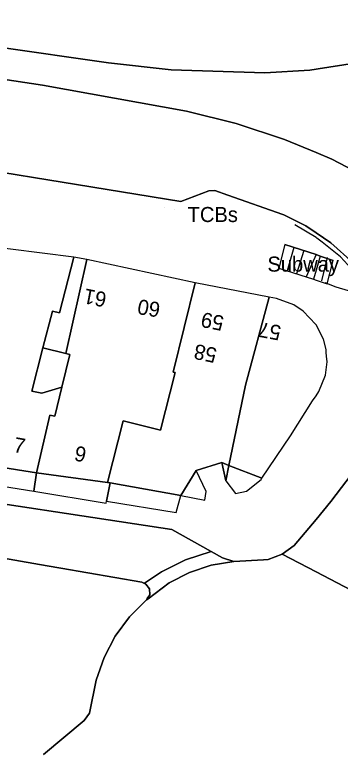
# Model space of a CAD drawing. Extents: x 529240 to 530363, y 179600 to 180767.
# Drawn here: x 529969.9 to 530002.4, y 180321.7 to 180395.2 of the extents above; entities that cross this region are included whole.
import ezdxf

# ---------------------------------------------------------------- set-up
doc = ezdxf.new("R2010")
doc.units = 0
for name, color, linetype in [('Building', 7, 'Continuous'), ('General surface', 7, 'Continuous'), ('Road Or Track', 7, 'Continuous'), ('Roadside', 7, 'Continuous'), ('Structure', 7, 'Continuous'), ('Unclassified', 7, 'Continuous')]:
    doc.layers.add(name, color=color, linetype=linetype)

msp = doc.modelspace()

# ---------------------------------------------------------------- linework, layer by layer
at = {"layer": 'Building'}
for points in [[(529968.1, 180350.2), (529972.1, 180349.55), (529973.45, 180355.3), (529973.95, 180355.2), (529974.65, 180358.1), (529972.65, 180357.5), (529971.65, 180357.7), (529972.75, 180362), (529973.7, 180365.65), (529974.4, 180365.5), (529975.85, 180371.05), (529960, 180373.05), (529957.55, 180360.3), (529963.4, 180359.2), (529962.95, 180357), (529962.5, 180357.05), (529961.45, 180351.2), (529964.45, 180350.75)], [(529979.2, 180348.6), (529980.75, 180354.75), (529984.5, 180353.8), (529985.95, 180359.55), (529985.75, 180359.6), (529987.95, 180368.5), (529977.15, 180370.8), (529975.05, 180361.45), (529975.45, 180361.35), (529974.65, 180358.1), (529973.95, 180355.2), (529973.45, 180355.3), (529972.1, 180349.55)], [(529977.15, 180370.8), (529975.85, 180371.05), (529974.4, 180365.5), (529973.7, 180365.65), (529972.75, 180362), (529975.05, 180361.45)], [(529979.45, 180348.55), (529986.5, 180347.3), (529988.05, 180349.8), (529990.6, 180350.6), (529991.3, 180350.3), (529992.95, 180358.3), (529995.33, 180367.05), (529987.95, 180368.5), (529985.75, 180359.6), (529985.95, 180359.55), (529984.5, 180353.8), (529980.75, 180354.75), (529979.2, 180348.6)], [(529999.65, 180356.74), (530000, 180357.24), (530000.28, 180357.66), (530000.93, 180359.29), (530001.1, 180360.6), (530001.05, 180361.18), (530001.02, 180361.56), (530001, 180361.86), (530000.73, 180362.89), (530000, 180364.31), (529999.99, 180364.33), (529998.73, 180365.67), (529997.78, 180366.3), (529996.06, 180366.91), (529995.33, 180367.05), (529992.95, 180358.3), (529991.3, 180350.3), (529994.59, 180349.02), (529997.44, 180353.25)]]:
    msp.add_lwpolyline(points, close=True, dxfattribs=at)
for points in [[(529975.85, 180371.05), (529960, 180373.05)], [(529972.75, 180362), (529973.7, 180365.65), (529974.4, 180365.5), (529975.85, 180371.05)], [(529975.05, 180361.45), (529977.15, 180370.8)], [(529977.15, 180370.8), (529975.85, 180371.05)], [(529987.95, 180368.5), (529977.15, 180370.8)], [(529979.2, 180348.6), (529980.75, 180354.75), (529984.5, 180353.8), (529985.95, 180359.55), (529985.75, 180359.6), (529987.95, 180368.5)], [(529995.33, 180367.05), (529987.95, 180368.5)], [(529995.33, 180367.05), (529992.95, 180358.3), (529991.3, 180350.3)], [(529999.65, 180356.74), (530000, 180357.24), (530000.28, 180357.66), (530000.93, 180359.29), (530001.1, 180360.6), (530001.05, 180361.18), (530001.02, 180361.56), (530001, 180361.86), (530000.73, 180362.89), (530000, 180364.31), (529999.99, 180364.33), (529998.73, 180365.67), (529997.78, 180366.3), (529996.06, 180366.91), (529995.33, 180367.05)], [(529974.65, 180358.1), (529972.65, 180357.5), (529971.65, 180357.7), (529972.75, 180362)], [(529975.05, 180361.45), (529972.75, 180362)], [(529974.65, 180358.1), (529975.45, 180361.35), (529975.05, 180361.45)], [(529972.1, 180349.55), (529973.45, 180355.3), (529973.95, 180355.2), (529974.65, 180358.1)], [(529994.59, 180349.02), (529997.44, 180353.25), (529999.65, 180356.74)], [(529968.1, 180350.2), (529972.1, 180349.55)], [(529990.6, 180350.6), (529988.05, 180349.8)], [(529991.3, 180350.3), (529990.6, 180350.6)], [(529994.59, 180349.02), (529991.3, 180350.3)], [(529972.1, 180349.55), (529979.2, 180348.6)], [(529988.05, 180349.8), (529986.5, 180347.3)], [(529979.2, 180348.6), (529979.45, 180348.55)], [(529979.45, 180348.55), (529986.5, 180347.3)]]:
    msp.add_lwpolyline(points, dxfattribs=at)
at = {"layer": 'General surface'}
for points in [[(529996.9, 180372.3), (529996.3, 180369.95), (529999.75, 180368.85), (530000, 180368.75), (530001.1, 180368.4), (530001.7, 180370.7), (530000.4, 180371.15), (530000, 180371.3)], [(529974.65, 180358.1), (529975.45, 180361.35), (529975.05, 180361.45), (529972.75, 180362), (529971.65, 180357.7), (529972.65, 180357.5)], [(529971.85, 180347.75), (529972.1, 180349.55), (529968.1, 180350.2), (529967.85, 180348.35)], [(529991.3, 180350.3), (529990.6, 180350.6), (529991, 180348.75)], [(529991.3, 180350.3), (529991, 180348.75), (529991.95, 180347.5), (529993.05, 180347.75), (529994.51, 180348.9), (529994.59, 180349.02)], [(529979.2, 180348.6), (529972.1, 180349.55), (529971.85, 180347.75), (529979.05, 180346.55), (529979.1, 180346.75), (529979.45, 180348.55)], [(529986.5, 180347.3), (529988.9, 180346.85), (529989.05, 180347.7), (529988.05, 180349.8)], [(529979.45, 180348.55), (529979.1, 180346.75), (529986.05, 180345.6), (529986.5, 180347.3)]]:
    msp.add_lwpolyline(points, close=True, dxfattribs=at)
for points in [[(529996.9, 180372.3), (529996.3, 180369.95)], [(529997.8, 180372.01), (529997.12, 180369.69)], [(529998.78, 180371.69), (529998.05, 180369.39)], [(530000, 180371.3), (529999, 180369.09)], [(530000.4, 180371.15), (530000, 180369.75), (529999.75, 180368.85)], [(530001.1, 180371), (530000.55, 180368.7)]]:
    msp.add_lwpolyline(points, dxfattribs=at)
at = {"layer": 'Road Or Track'}
for points in [[(529954.48, 180398.5), (529953.23, 180394.13), (529953.97, 180394.02), (529956.99, 180393.59), (529979.3, 180390.4), (529985.56, 180389.7), (529994.89, 180389.4), (529999.38, 180389.68), (530000, 180389.77), (530000.2, 180389.8), (530003.82, 180390.38), (530011.94, 180392.6), (530010.83, 180400.08)], [(530011.94, 180392.6), (530003.82, 180390.38), (530000.2, 180389.8), (530000, 180389.77), (529999.38, 180389.68), (529994.89, 180389.4), (529985.56, 180389.7), (529979.3, 180390.4), (529956.99, 180393.59), (529953.97, 180394.02), (529953.23, 180394.13)], [(529952.41, 180391.23), (529952.45, 180391.21), (529953.54, 180391.05), (529972.72, 180388.17), (529987.07, 180385.57), (529992.02, 180384.36), (529996.86, 180382.76), (530000, 180381.45), (530001.57, 180380.79), (530006.1, 180378.46)], [(529949.92, 180382.52), (529952.4, 180382.12), (529955.46, 180381.62), (529986.51, 180376.59), (529989.29, 180377.65), (529989.92, 180377.68), (529991.21, 180377.23), (529996.68, 180375.3), (529996.77, 180375.26), (529998.99, 180374.16), (530000, 180373.48), (530001.47, 180372.48), (530003.69, 180370.47), (530005.28, 180368.4)], [(530007.46, 180362.76), (530007.67, 180360.38), (530007.5, 180357.98), (530007.09, 180356.28), (530006.94, 180355.65), (530006.23, 180353.98), (530005.88, 180353.16), (530005.52, 180352.55), (530004.04, 180350.06), (530001.49, 180346.7), (530000, 180344.91), (529997.83, 180342.33), (529996.61, 180341.47)], [(529989.55, 180341.72), (529985.6, 180343.91), (529959.75, 180347.85), (529942.9, 180350.6), (529942.65, 180350.7), (529941.9, 180351.15)], [(530004.04, 180350.06), (530001.49, 180346.7), (530000, 180344.91), (529997.83, 180342.33), (529996.61, 180341.47), (530000, 180339.7), (530003.49, 180337.87)], [(529973.18, 180340.31), (529941.05, 180345.9), (529940.34, 180346.04)], [(530003.49, 180337.87), (530000, 180339.7), (529996.61, 180341.47), (529995.21, 180340.94), (529994.77, 180340.91), (529991.8, 180340.74), (529989.55, 180340.36), (529987.39, 180339.63), (529985.36, 180338.6), (529983.24, 180337.02), (529983.09, 180336.91), (529981.4, 180335.22), (529979.97, 180333.29), (529978.85, 180331.17), (529978.06, 180328.91), (529977.41, 180325.61), (529976.87, 180324.9), (529972.82, 180321.51)], [(529989.55, 180341.72), (529986.98, 180340.9), (529984.57, 180339.7), (529982.9, 180338.56), (529982.88, 180338.55)], [(529991.8, 180340.74), (529990.67, 180341.1), (529989.55, 180341.72)], [(529996.61, 180341.47), (529995.21, 180340.94), (529994.77, 180340.91), (529991.8, 180340.74)], [(529991.8, 180340.74), (529989.55, 180340.36), (529987.39, 180339.63), (529985.36, 180338.6), (529983.24, 180337.02), (529983.09, 180336.91)], [(529982.88, 180338.55), (529982.61, 180338.66), (529974.53, 180340.07), (529973.18, 180340.31)], [(529983.09, 180336.91), (529983.17, 180337.03), (529983.41, 180337.41), (529983.39, 180338.01), (529983.03, 180338.48), (529982.88, 180338.55)], [(529972.82, 180321.51), (529976.87, 180324.9), (529977.41, 180325.61), (529978.06, 180328.91), (529978.85, 180331.17), (529979.97, 180333.29), (529981.4, 180335.22), (529983.09, 180336.91)]]:
    msp.add_lwpolyline(points, dxfattribs=at)
for points in [[(530005.28, 180368.4), (530006.1, 180378.46), (530001.57, 180380.79), (530000, 180381.45), (529996.86, 180382.76), (529992.02, 180384.36), (529987.07, 180385.57), (529972.72, 180388.17), (529953.54, 180391.05), (529952.45, 180391.21), (529952.41, 180391.23), (529949.92, 180382.52), (529952.4, 180382.12), (529955.46, 180381.62), (529986.51, 180376.59), (529989.29, 180377.65), (529989.92, 180377.68), (529991.21, 180377.23), (529996.68, 180375.3), (529996.77, 180375.26), (529998.99, 180374.16), (530000, 180373.48), (530001.47, 180372.48), (530003.69, 180370.47)], [(529940.34, 180346.04), (529941.05, 180345.9), (529973.18, 180340.31), (529974.53, 180340.07), (529982.61, 180338.66), (529982.88, 180338.55), (529982.9, 180338.56), (529984.57, 180339.7), (529986.98, 180340.9), (529989.55, 180341.72), (529985.6, 180343.91), (529959.75, 180347.85), (529942.9, 180350.6), (529942.65, 180350.7), (529941.9, 180351.15)], [(529983.09, 180336.91), (529983.24, 180337.02), (529985.36, 180338.6), (529987.39, 180339.63), (529989.55, 180340.36), (529991.8, 180340.74), (529990.67, 180341.1), (529989.55, 180341.72), (529986.98, 180340.9), (529984.57, 180339.7), (529982.9, 180338.56), (529982.88, 180338.55), (529983.03, 180338.48), (529983.39, 180338.01), (529983.41, 180337.41), (529983.17, 180337.03)]]:
    msp.add_lwpolyline(points, close=True, dxfattribs=at)
at = {"layer": 'Roadside'}
for points in [[(530003.82, 180390.38), (530000.2, 180389.8), (530000, 180389.77), (529999.38, 180389.68), (529994.89, 180389.4), (529985.56, 180389.7), (529979.3, 180390.4), (529956.99, 180393.59)], [(529953.54, 180391.05), (529972.72, 180388.17), (529987.07, 180385.57), (529992.02, 180384.36), (529996.86, 180382.76), (530000, 180381.45), (530001.57, 180380.79), (530006.1, 180378.46)], [(530003.69, 180370.47), (530001.47, 180372.48), (530000, 180373.48), (529998.99, 180374.16), (529996.77, 180375.26), (529996.68, 180375.3), (529991.21, 180377.23), (529989.92, 180377.68), (529989.29, 180377.65), (529986.51, 180376.59), (529955.46, 180381.62)], [(529967.85, 180348.35), (529971.85, 180347.75), (529979.05, 180346.55), (529979.1, 180346.75), (529986.05, 180345.6), (529986.5, 180347.3), (529988.9, 180346.85), (529989.05, 180347.7), (529988.05, 180349.8), (529990.6, 180350.6), (529991, 180348.75), (529991.95, 180347.5), (529993.05, 180347.75), (529994.51, 180348.9), (529994.59, 180349.02), (529997.44, 180353.25), (529999.65, 180356.74), (530000, 180357.24), (530000.28, 180357.66), (530000.93, 180359.29), (530001.1, 180360.6), (530001.05, 180361.18), (530001.02, 180361.56), (530001, 180361.86), (530000.73, 180362.89), (530000, 180364.31), (529999.99, 180364.33), (529998.73, 180365.67), (529997.78, 180366.3), (529996.06, 180366.91), (529995.33, 180367.05), (529987.95, 180368.5), (529977.15, 180370.8), (529975.85, 180371.05), (529960, 180373.05)], [(529959.75, 180347.85), (529985.6, 180343.91), (529989.55, 180341.72), (529990.67, 180341.1), (529991.8, 180340.74), (529994.77, 180340.91), (529995.21, 180340.94), (529996.61, 180341.47), (529997.83, 180342.33), (530000, 180344.91), (530001.49, 180346.7), (530004.04, 180350.06)], [(529972.82, 180321.51), (529976.87, 180324.9), (529977.41, 180325.61), (529978.06, 180328.91), (529978.85, 180331.17), (529979.97, 180333.29), (529981.4, 180335.22), (529983.09, 180336.91), (529983.17, 180337.03), (529983.41, 180337.41), (529983.39, 180338.01), (529983.03, 180338.48), (529982.88, 180338.55), (529982.61, 180338.66), (529974.53, 180340.07), (529973.18, 180340.31), (529941.05, 180345.9)]]:
    msp.add_lwpolyline(points, dxfattribs=at)
msp.add_lwpolyline([(530000, 180371.3), (529996.9, 180372.3), (529996.3, 180369.95), (529999.75, 180368.85), (530000, 180368.75), (530001.1, 180368.4), (530001.7, 180370.7), (530000.4, 180371.15)], close=True, dxfattribs=at)
at = {"layer": 'Structure'}
for p, q in [((529984.89, 180375.94), (529984.89, 180375.94)), ((529985.87, 180375.78), (529985.87, 180375.78))]:
    msp.add_line(p, q, dxfattribs=at)
at = {"layer": 'Unclassified'}
for points in [[(530007, 180357.74), (530007.22, 180360.13), (530007.05, 180362.52), (530006.48, 180364.85), (530005.55, 180367.06), (530004.29, 180369.06), (530004.27, 180369.09), (530002.44, 180371.07), (530000.6, 180372.52), (530000.09, 180372.93), (530000, 180372.99), (529997.87, 180374.25)], [(529996.9, 180372.3), (530000, 180371.3)], [(530000, 180371.3), (530000.4, 180371.15), (530001.7, 180370.7)], [(529999.75, 180368.85), (530000, 180368.75), (530001.1, 180368.4), (530001.7, 180370.7)], [(529996.3, 180369.95), (529999.75, 180368.85)], [(530003.25, 180367.7), (530002, 180368.05), (530000.9, 180368.5)], [(529991, 180348.75), (529990.6, 180350.6)], [(529991, 180348.75), (529991.3, 180350.3)], [(529971.85, 180347.75), (529972.1, 180349.55)], [(529988.9, 180346.85), (529989.05, 180347.7), (529988.05, 180349.8)], [(529979.1, 180346.75), (529979.45, 180348.55)], [(529991, 180348.75), (529991.95, 180347.5), (529993.05, 180347.75), (529994.51, 180348.9), (529994.59, 180349.02)], [(529967.85, 180348.35), (529971.85, 180347.75)], [(529971.85, 180347.75), (529979.05, 180346.55), (529979.1, 180346.75)], [(529979.1, 180346.75), (529986.05, 180345.6), (529986.5, 180347.3)], [(529986.5, 180347.3), (529988.9, 180346.85)], [(530003.49, 180337.87), (530000, 180339.7), (529996.61, 180341.47)]]:
    msp.add_lwpolyline(points, dxfattribs=at)

# ---------------------------------------------------------------- texts
at = {"layer": 'Structure'}
for s, p in [('TCBs', (529987.19, 180374.54)), ('Subway', (529995.15, 180369.6))]:
    msp.add_text(s, height=1.5, dxfattribs=at).set_placement(p)
at = {"layer": 'Unclassified'}
for s, rotation, p in [('61', 169, (529979.2, 180367.5)), ('60', 170.3, (529984.55, 180366.5)), ('59', 168.7, (529990.9, 180365.15)), ('57', 169.5, (529996.6, 180364.2)), ('58', 168.1, (529990.2, 180361.95)), ('7', 349.8, (529969.75, 180351.65)), ('9', 348.8, (529975.8, 180350.8))]:
    msp.add_text(s, height=1.5, rotation=rotation, dxfattribs=at).set_placement(p)

doc.saveas('drawing.dxf')
